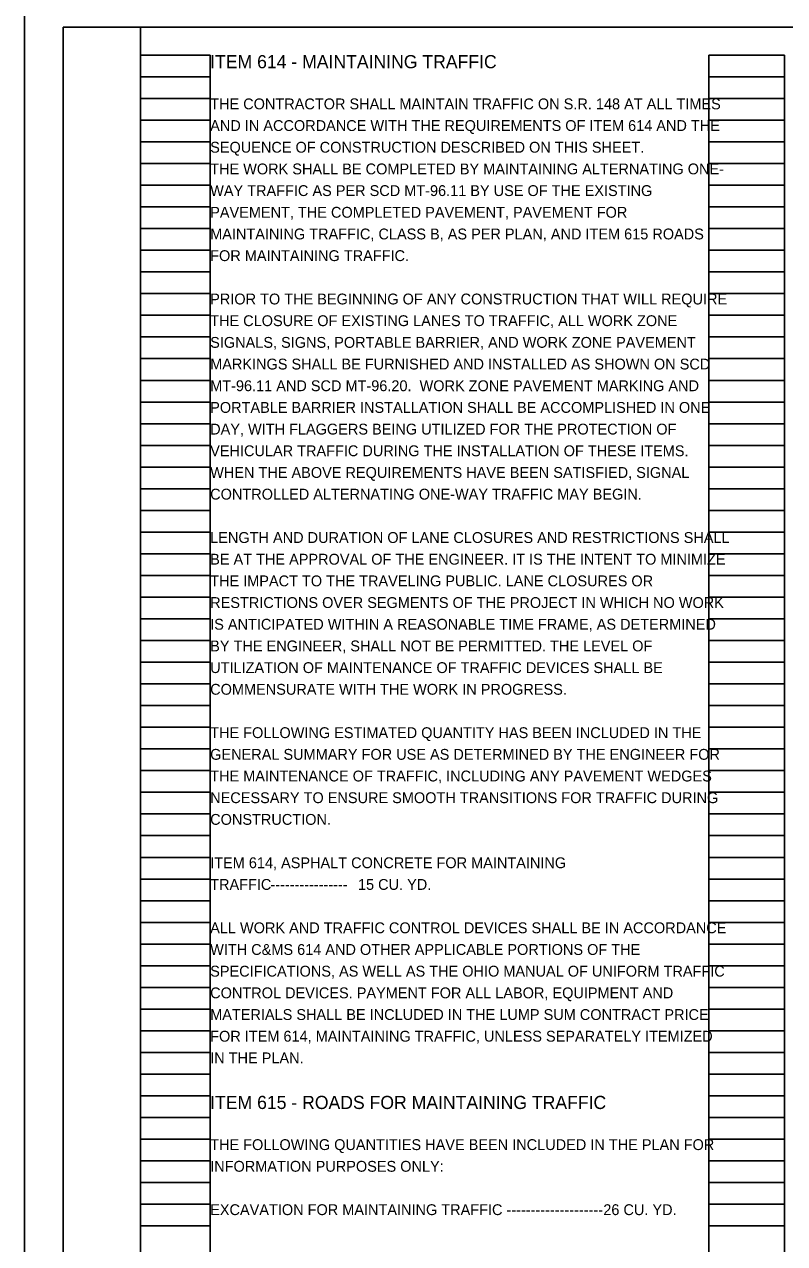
# Model space of a CAD drawing. Extents: x -7.5 to 46.3, y -5.1 to 34.9.
# Drawn here: x 0 to 9.82, y 5.79 to 21.54 of the extents above; entities that cross this region are included whole.
import ezdxf

# ---------------------------------------------------------------- set-up
doc = ezdxf.new("R2010")
doc.units = 0
for name, color, linetype in [('SH_Border', 7, 'Continuous'), ('SH_Cut_Line', 7, 'Continuous'), ('SH_Data', 7, 'Continuous'), ('SH_Text', 7, 'Continuous')]:
    doc.layers.add(name, color=color, linetype=linetype)

msp = doc.modelspace()

# ---------------------------------------------------------------- linework, layer by layer
at = {"layer": 'SH_Border'}
for points in [[(0.5, 21.5), (1.5, 21.5), (1.5, 0.5), (0.5, 0.5)], [(1.5, 21.5), (33.5, 21.5), (33.5, 0.5), (1.5, 0.5)]]:
    msp.add_lwpolyline(points, close=True, dxfattribs=at)
at = {"layer": 'SH_Cut_Line'}
msp.add_lwpolyline([(0, 0), (34, 0), (34, 22), (0, 22)], close=True, dxfattribs=at)
at = {"layer": 'SH_Data'}
for p, q in [((1.5, 0.98), (1.5, 21.14)), ((1.5, 21.14), (2.4, 21.14)), ((2.4, 0.98), (2.4, 21.14)), ((8.84, 0.98), (8.84, 21.14)), ((8.84, 21.14), (9.82, 21.14)), ((9.82, 0.98), (9.82, 21.14)), ((1.5, 20.86), (2.4, 20.86)), ((8.84, 20.86), (9.82, 20.86)), ((1.5, 20.58), (2.4, 20.58)), ((8.84, 20.58), (9.82, 20.58)), ((1.5, 20.3), (2.4, 20.3)), ((8.84, 20.3), (9.82, 20.3)), ((1.5, 20.02), (2.4, 20.02)), ((8.84, 20.02), (9.82, 20.02)), ((1.5, 19.74), (2.4, 19.74)), ((8.84, 19.74), (9.82, 19.74)), ((1.5, 19.46), (2.4, 19.46)), ((8.84, 19.46), (9.82, 19.46)), ((1.5, 19.18), (2.4, 19.18)), ((8.84, 19.18), (9.82, 19.18)), ((1.5, 18.9), (2.4, 18.9)), ((8.84, 18.9), (9.82, 18.9)), ((1.5, 18.62), (2.4, 18.62)), ((8.84, 18.62), (9.82, 18.62)), ((1.5, 18.34), (2.4, 18.34)), ((8.84, 18.34), (9.82, 18.34)), ((1.5, 18.06), (2.4, 18.06)), ((8.84, 18.06), (9.82, 18.06)), ((1.5, 17.78), (2.4, 17.78)), ((8.84, 17.78), (9.82, 17.78)), ((1.5, 17.5), (2.4, 17.5)), ((8.84, 17.5), (9.82, 17.5)), ((1.5, 17.22), (2.4, 17.22)), ((8.84, 17.22), (9.82, 17.22)), ((1.5, 16.94), (2.4, 16.94)), ((8.84, 16.94), (9.82, 16.94)), ((1.5, 16.66), (2.4, 16.66)), ((8.84, 16.66), (9.82, 16.66)), ((1.5, 16.38), (2.4, 16.38)), ((8.84, 16.38), (9.82, 16.38)), ((1.5, 16.1), (2.4, 16.1)), ((8.84, 16.1), (9.82, 16.1)), ((1.5, 15.82), (2.4, 15.82)), ((8.84, 15.82), (9.82, 15.82)), ((1.5, 15.54), (2.4, 15.54)), ((8.84, 15.54), (9.82, 15.54)), ((1.5, 15.26), (2.4, 15.26)), ((8.84, 15.26), (9.82, 15.26)), ((1.5, 14.98), (2.4, 14.98)), ((8.84, 14.98), (9.82, 14.98)), ((1.5, 14.7), (2.4, 14.7)), ((8.84, 14.7), (9.82, 14.7)), ((1.5, 14.42), (2.4, 14.42)), ((8.84, 14.42), (9.82, 14.42)), ((1.5, 14.14), (2.4, 14.14)), ((8.84, 14.14), (9.82, 14.14)), ((1.5, 13.86), (2.4, 13.86)), ((8.84, 13.86), (9.82, 13.86)), ((1.5, 13.58), (2.4, 13.58)), ((8.84, 13.58), (9.82, 13.58)), ((1.5, 13.3), (2.4, 13.3)), ((8.84, 13.3), (9.82, 13.3)), ((1.5, 13.02), (2.4, 13.02)), ((8.84, 13.02), (9.82, 13.02)), ((1.5, 12.74), (2.4, 12.74)), ((8.84, 12.74), (9.82, 12.74)), ((1.5, 12.46), (2.4, 12.46)), ((8.84, 12.46), (9.82, 12.46)), ((1.5, 12.18), (2.4, 12.18)), ((8.84, 12.18), (9.82, 12.18)), ((1.5, 11.9), (2.4, 11.9)), ((8.84, 11.9), (9.82, 11.9)), ((1.5, 11.62), (2.4, 11.62)), ((8.84, 11.62), (9.82, 11.62)), ((1.5, 11.34), (2.4, 11.34)), ((8.84, 11.34), (9.82, 11.34)), ((1.5, 11.06), (2.4, 11.06)), ((8.84, 11.06), (9.82, 11.06)), ((1.5, 10.78), (2.4, 10.78)), ((8.84, 10.78), (9.82, 10.78)), ((1.5, 10.5), (2.4, 10.5)), ((8.84, 10.5), (9.82, 10.5)), ((1.5, 10.22), (2.4, 10.22)), ((8.84, 10.22), (9.82, 10.22)), ((1.5, 9.94), (2.4, 9.94)), ((8.84, 9.94), (9.82, 9.94)), ((1.5, 9.66), (2.4, 9.66)), ((8.84, 9.66), (9.82, 9.66)), ((1.5, 9.38), (2.4, 9.38)), ((8.84, 9.38), (9.82, 9.38)), ((1.5, 9.1), (2.4, 9.1)), ((8.84, 9.1), (9.82, 9.1)), ((1.5, 8.82), (2.4, 8.82)), ((8.84, 8.82), (9.82, 8.82)), ((1.5, 8.54), (2.4, 8.54)), ((8.84, 8.54), (9.82, 8.54)), ((1.5, 8.26), (2.4, 8.26)), ((8.84, 8.26), (9.82, 8.26)), ((1.5, 7.98), (2.4, 7.98)), ((8.84, 7.98), (9.82, 7.98)), ((1.5, 7.7), (2.4, 7.7)), ((8.84, 7.7), (9.82, 7.7)), ((1.5, 7.42), (2.4, 7.42)), ((8.84, 7.42), (9.82, 7.42)), ((1.5, 7.14), (2.4, 7.14)), ((8.84, 7.14), (9.82, 7.14)), ((1.5, 6.86), (2.4, 6.86)), ((8.84, 6.86), (9.82, 6.86)), ((1.5, 6.58), (2.4, 6.58)), ((8.84, 6.58), (9.82, 6.58)), ((1.5, 6.3), (2.4, 6.3)), ((8.84, 6.3), (9.82, 6.3)), ((1.5, 6.02), (2.4, 6.02)), ((8.84, 6.02), (9.82, 6.02))]:
    msp.add_line(p, q, dxfattribs=at)

# ---------------------------------------------------------------- texts
at = {"layer": 'SH_Text'}
for s, height, p in [('ITEM 614 - MAINTAINING TRAFFIC', 0.17, (2.4, 20.97)), ('THE CONTRACTOR SHALL MAINTAIN TRAFFIC ON S.R. 148 AT ALL TIMES ', 0.14, (2.4, 20.44)), ('AND IN ACCORDANCE WITH THE REQUIREMENTS OF ITEM 614 AND THE ', 0.14, (2.4, 20.16)), ('SEQUENCE OF CONSTRUCTION DESCRIBED ON THIS SHEET.', 0.14, (2.4, 19.88)), ('THE WORK SHALL BE COMPLETED BY MAINTAINING ALTERNATING ONE-', 0.14, (2.4, 19.6)), ('WAY TRAFFIC AS PER SCD MT-96.11 BY USE OF THE EXISTING ', 0.14, (2.4, 19.32)), ('PAVEMENT, THE COMPLETED PAVEMENT, PAVEMENT FOR ', 0.14, (2.4, 19.04)), ('MAINTAINING TRAFFIC, CLASS B, AS PER PLAN, AND ITEM 615 ROADS ', 0.14, (2.4, 18.76)), ('FOR MAINTAINING TRAFFIC.', 0.14, (2.4, 18.48)), ('PRIOR TO THE BEGINNING OF ANY CONSTRUCTION THAT WILL REQUIRE ', 0.14, (2.4, 17.92)), ('THE CLOSURE OF EXISTING LANES TO TRAFFIC, ALL WORK ZONE ', 0.14, (2.4, 17.64)), ('SIGNALS, SIGNS, PORTABLE BARRIER, AND WORK ZONE PAVEMENT ', 0.14, (2.4, 17.36)), ('MARKINGS SHALL BE FURNISHED AND INSTALLED AS SHOWN ON SCD ', 0.14, (2.4, 17.08)), ('MT-96.11 AND SCD MT-96.20.  WORK ZONE PAVEMENT MARKING AND ', 0.14, (2.4, 16.8)), ('PORTABLE BARRIER INSTALLATION SHALL BE ACCOMPLISHED IN ONE ', 0.14, (2.4, 16.52)), ('DAY, WITH FLAGGERS BEING UTILIZED FOR THE PROTECTION OF ', 0.14, (2.4, 16.24)), ('VEHICULAR TRAFFIC DURING THE INSTALLATION OF THESE ITEMS.  ', 0.14, (2.4, 15.96)), ('WHEN THE ABOVE REQUIREMENTS HAVE BEEN SATISFIED, SIGNAL ', 0.14, (2.4, 15.68)), ('CONTROLLED ALTERNATING ONE-WAY TRAFFIC MAY BEGIN.', 0.14, (2.4, 15.4)), ('LENGTH AND DURATION OF LANE CLOSURES AND RESTRICTIONS SHALL ', 0.14, (2.4, 14.84)), ('BE AT THE APPROVAL OF THE ENGINEER. IT IS THE INTENT TO MINIMIZE ', 0.14, (2.4, 14.56)), ('THE IMPACT TO THE TRAVELING PUBLIC. LANE CLOSURES OR ', 0.14, (2.4, 14.28)), ('RESTRICTIONS OVER SEGMENTS OF THE PROJECT IN WHICH NO WORK ', 0.14, (2.4, 14)), ('IS ANTICIPATED WITHIN A REASONABLE TIME FRAME, AS DETERMINED ', 0.14, (2.4, 13.72)), ('BY THE ENGINEER, SHALL NOT BE PERMITTED. THE LEVEL OF ', 0.14, (2.4, 13.44)), ('UTILIZATION OF MAINTENANCE OF TRAFFIC DEVICES SHALL BE ', 0.14, (2.4, 13.16)), ('COMMENSURATE WITH THE WORK IN PROGRESS.', 0.14, (2.4, 12.88)), ('THE FOLLOWING ESTIMATED QUANTITY HAS BEEN INCLUDED IN THE ', 0.14, (2.4, 12.32)), ('GENERAL SUMMARY FOR USE AS DETERMINED BY THE ENGINEER FOR ', 0.14, (2.4, 12.04)), ('THE MAINTENANCE OF TRAFFIC, INCLUDING ANY PAVEMENT WEDGES ', 0.14, (2.4, 11.76)), ('NECESSARY TO ENSURE SMOOTH TRANSITIONS FOR TRAFFIC DURING ', 0.14, (2.4, 11.48)), ('CONSTRUCTION.', 0.14, (2.4, 11.2)), ('ITEM 614, ASPHALT CONCRETE FOR MAINTAINING ', 0.14, (2.4, 10.64)), ('TRAFFIC ', 0.14, (2.4, 10.36)), ('----------------', 0.14, (3.178, 10.36)), ('15 CU. YD.', 0.14, (4.309, 10.36)), ('ALL WORK AND TRAFFIC CONTROL DEVICES SHALL BE IN ACCORDANCE ', 0.14, (2.4, 9.8)), ('WITH C&MS 614 AND OTHER APPLICABLE PORTIONS OF THE ', 0.14, (2.4, 9.52)), ('SPECIFICATIONS, AS WELL AS THE OHIO MANUAL OF UNIFORM TRAFFIC ', 0.14, (2.4, 9.24)), ('CONTROL DEVICES. PAYMENT FOR ALL LABOR, EQUIPMENT AND ', 0.14, (2.4, 8.96)), ('MATERIALS SHALL BE INCLUDED IN THE LUMP SUM CONTRACT PRICE ', 0.14, (2.4, 8.68)), ('FOR ITEM 614, MAINTAINING TRAFFIC, UNLESS SEPARATELY ITEMIZED ', 0.14, (2.4, 8.4)), ('IN THE PLAN.', 0.14, (2.4, 8.12)), ('ITEM 615 - ROADS FOR MAINTAINING TRAFFIC', 0.17, (2.4, 7.53)), ('THE FOLLOWING QUANTITIES HAVE BEEN INCLUDED IN THE PLAN FOR ', 0.14, (2.4, 7)), ('INFORMATION PURPOSES ONLY:', 0.14, (2.4, 6.72)), ('EXCAVATION FOR MAINTAINING TRAFFIC -------------------- ', 0.14, (2.4, 6.16)), ('26 CU. YD.', 0.14, (7.478, 6.16))]:
    msp.add_text(s, height=height, dxfattribs=at).set_placement(p)

doc.saveas('drawing.dxf')
